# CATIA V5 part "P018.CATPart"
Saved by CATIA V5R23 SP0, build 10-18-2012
Part number: 05-LICP-T02-E-S05-P018
Bounding box of the stored display mesh (mm): x -10 to 10, y -59.995 to 38.595, z -23.995 to 55.885
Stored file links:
  C:\wamp\www\COURS\CONCEPTION GMP1\TITRE 02-SEMESTRE 2\03-TP7-PRESSE MECANIQUE\eleve\P018.CATPart
  C:\wamp\www\COURS\CONCEPTION GMP1\TITRE 02-SEMESTRE 2\03-TP7-PRESSE MECANIQUE\eleve\05-LICP-T02-E-S05-P018.CATPart
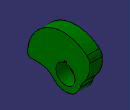
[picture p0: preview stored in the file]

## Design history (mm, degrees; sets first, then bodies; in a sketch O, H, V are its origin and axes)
Body1 (main body)
  Sketch1 on yz-plane, origin (0, 0, 0), H (0, 1, 0), V (0, 0, 1)
    arc A1 centre (-3.0096, -1.0752) radius 57 from (33.9064, 42.3552) to (-59.9946, 0.2327) ccw
    point P2 (33.9064, 42.3552)
    point P3 (-59.9946, 0.2327)
    reference intersected line E1 through (0, 0) direction (-1, 0) from xy-plane
    reference intersected line E2 through (0, 0) direction (-1, 0) from xy-plane
    reference intersected line E3 through (0, 0) direction (0, 1) from zx-plane
    arc A2 centre (25.487, 32.4501) radius 13 from (38.4345, 33.6163) to (33.9064, 42.3552) ccw
    point P5 (38.4345, 33.6163)
    point P6 (33.9064, 42.3552)
    arc A3 centre (-1.4042, 30.0278) radius 40 from (29.5672, 4.7144) to (38.4345, 33.6163) ccw
    point P8 (29.5672, 4.7144)
    point P9 (38.4345, 33.6163)
    reference intersected line E4 through (0, 0) direction (-1, 0) from xy-plane
    arc A4 centre (51.7244, -15.5109) radius 30 from (29.5672, 4.7144) to (22.9886, -6.8937) ccw
    point P11 (29.5672, 4.7144)
    point P12 (22.9886, -6.8937)
    arc A5 centre (-40.9422, -35.2099) radius 30 from (-18.1965, -15.6489) to (-41.2591, -5.2116) ccw
    point P14 (-18.1965, -15.6489)
    point P15 (-41.2591, -5.2116)
    reference intersected line E5 through (0, 0) direction (-1, 0) from xy-plane
    reference intersected line E6 through (0, 0) direction (0, 1) from zx-plane
    reference intersected line E7 through (0, 0) direction (-1, 0) from xy-plane
    reference intersected line E8 through (0, 0) direction (0, 1) from zx-plane
    arc A6 centre (0, 0) radius 24 from (-18.1965, -15.6489) to (22.9886, -6.8937) ccw
    point P17 (-18.1965, -15.6489)
    point P18 (22.9886, -6.8937)
    reference intersected line E9 through (0, 0) direction (-1, 0) from xy-plane
    arc A7 centre (-55.2011, -0.0167) radius 4.8 from (-59.9946, 0.2327) to (-55.5793, -4.8017) ccw
    point P20 (-59.9946, 0.2327)
    point P21 (-55.5793, -4.8017)
    reference intersected line E10 through (0, 0) direction (-1, 0) from xy-plane
    arc A8 centre (-43.1818, 177.9833) radius 183.205 from (-55.5793, -4.8017) to (-41.2591, -5.2116) ccw
    point P23 (-55.5793, -4.8017)
    point P24 (-41.2591, -5.2116)
    reference intersected line E11 through (0, 0) direction (-1, 0) from xy-plane
    radius A1 = 57
    distance P2 E1 = 42.3552
    distance E2 P3 = 0.2327
    distance E3 P3 = 59.9946
    radius A2 = 13
    distance P5 E4 = 33.6163
    radius A3 = 40
    radius A4 = 30
    distance P8 E5 = 4.7144
    distance E6 P8 = 29.5672
    distance E7 P12 = 6.8937
    distance P12 E8 = 22.9886
    radius A6 = 24
    distance V P17 = 18.1965
    distance E9 P17 = 15.6489
    distance P21 V = 55.5793
    radius A7 = 4.8
    radius A5 = 30
    distance P15 E10 = 5.2116
    radius A8 = 183.205
    distance P21 E11 = 4.8017
    distance P15 V = 41.2591
    coincidence: P6 P2, P9 P5, P8 P11, P18 P12, P3 P20, P14 P17, P15 P24, P23 P21
    tangency: A2 A1, A2 A3
  Sketch2 on yz-plane, origin (0, 0, 0), H (0, 1, 0), V (0, 0, 1)
    arc A1 centre (0, 0) radius 15 from (-2, 14.8661) to (2, 14.8661) ccw
    line L1 (-2, 14.8661) -> (-2, 18)
    line L2 (-2, 18) -> (2, 18)
    line L3 (2, 18) -> (2, 14.8661)
    reference intersected line E1 through (0, 0) direction (-1, 0) from xy-plane
    distance L2 E1 = 18
    length L2 = 4
    radius A1 = 15
    vertical: L1 V, L3 V
    horizontal: L2 H
    symmetry: L3 L1 V
  Pad1: profile Sketch1, direction (1, 0, 0), length 10, mirrored extent
  Pocket1: profile Sketch2, direction (-1, 0, 0), through (limit type 3), opposite side through (limit type 3)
